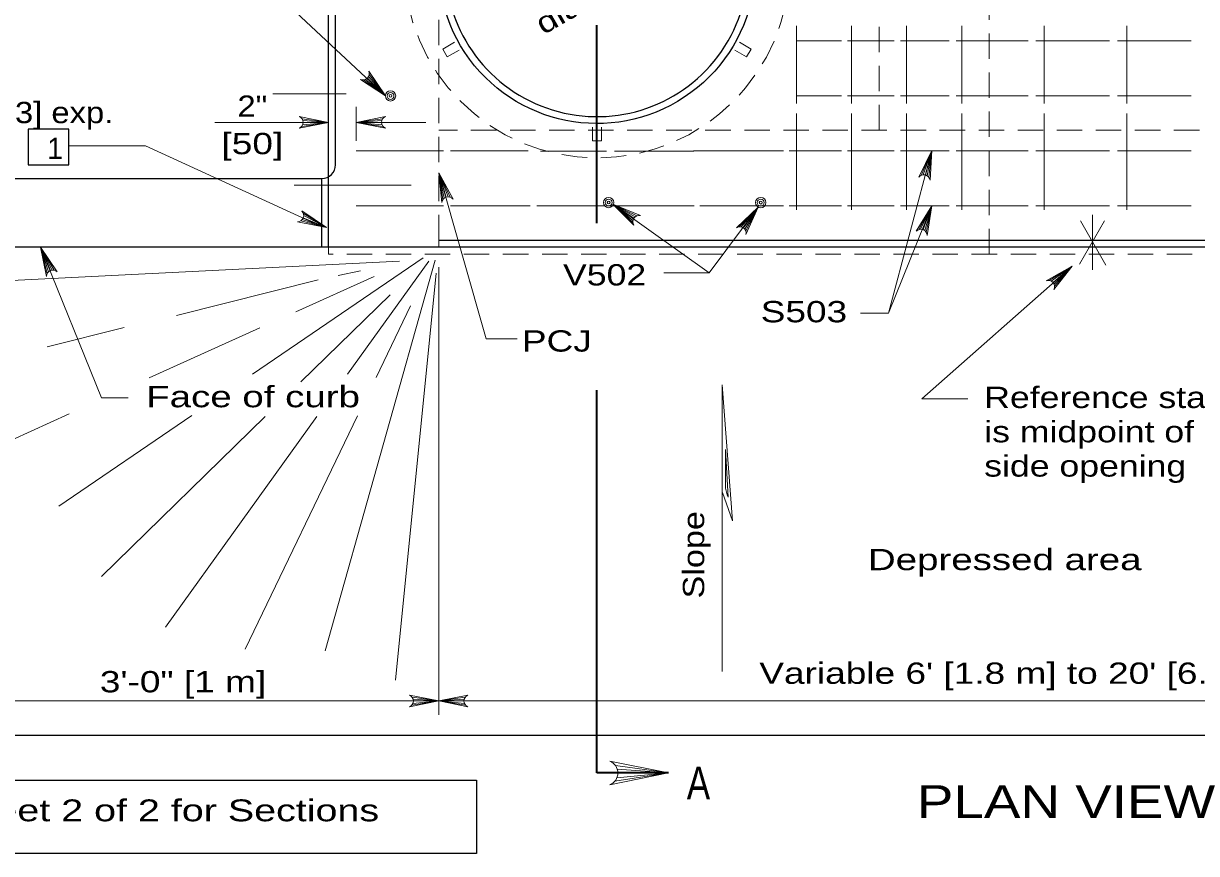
# Model space of a CAD drawing. Extents: x 758.3 to 792.3, y 849.7 to 893.7.
# Drawn here: x 762.67 to 771.26, y 882.61 to 888.69 of the extents above; entities that cross this region are included whole.
import ezdxf
from ezdxf.enums import TextEntityAlignment as Align

# ---------------------------------------------------------------- set-up
doc = ezdxf.new("R2010")
doc.units = 0
doc.header["$LTSCALE"] = 0.062
doc.linetypes.add('DOTTED', pattern=[1.5, 0.3, -1.2])
doc.linetypes.add('MEDIUM_DASHED', pattern=[4.5, 3, -1.5])
doc.layers.add('1', color=7, linetype='Continuous', lineweight=13)

msp = doc.modelspace()

# ---------------------------------------------------------------- linework, layer by layer
at = {"layer": '1', "lineweight": 25}
for p, q in [((764.9015, 887.05092), (764.9015, 891.08192)), ((764.95183, 887.65558), (764.95183, 891.0315)), ((761.99533, 887.55475), (764.85108, 887.55475)), ((764.85108, 887.05092), (764.85108, 887.55475)), ((775.28242, 887.10125), (765.70775, 887.10125)), ((767.821, 883.47342), (761.29283, 883.47342))]:
    msp.add_line(p, q, dxfattribs=at)
at = {"layer": '1', "linetype": 'MEDIUM_DASHED'}
for p, q in [((769.73917, 887.0005), (769.73917, 891.02758)), ((765.70775, 887.10125), (765.70775, 890.32608)), ((768.93292, 887.9075), (768.93292, 890.32608)), ((775.28242, 887.9075), (765.70775, 887.9075)), ((764.9015, 887.0005), (764.9015, 887.05092)), ((776.08867, 887.0005), (764.9015, 887.0005))]:
    msp.add_line(p, q, dxfattribs=at)
at = {"layer": '1'}
for p, q in [((765.31725, 888.15942), (764.66508, 888.76933)), ((768.32817, 888.10433), (768.32817, 888.67275)), ((768.73133, 888.10433), (768.73133, 888.67275)), ((769.1345, 888.10433), (769.1345, 888.67275)), ((769.53758, 888.10433), (769.53758, 888.67275)), ((770.14233, 888.10433), (770.14233, 888.67275)), ((770.74708, 888.10433), (770.74708, 888.67275)), ((768.65858, 888.5625), (768.32817, 888.5625)), ((769.04258, 888.5625), (768.70133, 888.5625)), ((769.4455, 888.5625), (769.09, 888.5625)), ((770.02392, 888.5625), (769.49775, 888.5625)), ((770.62125, 888.5625), (770.08075, 888.5625)), ((771.2185, 888.5625), (770.67808, 888.5625)), ((765.157, 888.27658), (765.31725, 888.15942)), ((765.17117, 888.28025), (765.31725, 888.15942)), ((765.18592, 888.29017), (765.31725, 888.15942)), ((765.19417, 888.30133), (765.31725, 888.15942)), ((765.19892, 888.3155), (765.31725, 888.15942)), ((764.49267, 888.17475), (765.03125, 888.17475)), ((768.65858, 888.15942), (768.32817, 888.15942)), ((769.04258, 888.15942), (768.70133, 888.15942)), ((769.4455, 888.15942), (769.09, 888.15942)), ((770.02392, 888.15942), (769.49775, 888.15942)), ((770.62125, 888.15942), (770.08075, 888.15942)), ((771.2185, 888.15942), (770.67808, 888.15942)), ((765.10308, 887.82992), (765.10308, 888.07867)), ((764.70758, 887.99258), (764.9015, 887.96542)), ((765.29692, 887.99258), (765.10308, 887.96542)), ((768.32817, 887.32383), (768.32817, 888.03133)), ((768.73133, 887.32383), (768.73133, 888.03133)), ((769.1345, 887.32383), (769.1345, 888.03133)), ((769.53758, 887.32383), (769.53758, 888.03133)), ((770.14233, 887.32383), (770.14233, 888.03133)), ((770.74708, 887.32383), (770.74708, 888.03133)), ((764.9015, 887.96542), (764.06942, 887.96542)), ((764.70533, 887.93542), (764.9015, 887.96542)), ((764.71275, 887.948), (764.9015, 887.96542)), ((764.71417, 887.97917), (764.9015, 887.96542)), ((764.71617, 887.96542), (764.9015, 887.96542)), ((765.29033, 887.97917), (765.10308, 887.96542)), ((765.614, 887.96542), (765.10308, 887.96542)), ((765.28833, 887.96542), (765.10308, 887.96542)), ((765.29183, 887.948), (765.10308, 887.96542)), ((765.29925, 887.93542), (765.10308, 887.96542)), ((765.74292, 887.75633), (765.10308, 887.75633)), ((766.364, 887.75633), (765.795, 887.75633)), ((766.93733, 887.75558), (766.45375, 887.75558)), ((767.57733, 887.75558), (766.99425, 887.75558)), ((768.23183, 887.75633), (767.57283, 887.75633)), ((768.65858, 887.75633), (768.2745, 887.75633)), ((769.04258, 887.75633), (768.70133, 887.75633)), ((769.31983, 887.75925), (769.00292, 886.569)), ((769.4455, 887.75633), (769.09, 887.75633)), ((769.24083, 887.57717), (769.31983, 887.75925)), ((769.25492, 887.58117), (769.31983, 887.75925)), ((769.27258, 887.58), (769.31983, 887.75925)), ((769.28533, 887.57458), (769.31983, 887.75925)), ((769.29667, 887.56483), (769.31983, 887.75925)), ((770.02392, 887.75633), (769.49775, 887.75633)), ((770.62125, 887.75633), (770.08075, 887.75633)), ((771.2185, 887.75633), (770.67808, 887.75633)), ((765.76358, 887.41825), (765.71, 887.59567)), ((765.74792, 887.41), (765.71, 887.59567)), ((765.738, 887.39925), (765.71, 887.59567)), ((765.77725, 887.42033), (765.71, 887.59567)), ((765.792, 887.41792), (765.71, 887.59567)), ((764.6495, 887.50442), (765.50617, 887.50442)), ((764.71708, 887.29767), (764.88717, 887.19533)), ((765.74292, 887.35325), (765.10308, 887.35325)), ((766.37817, 887.35325), (765.795, 887.35325)), ((766.91858, 887.35325), (766.42558, 887.35325)), ((767.5775, 887.35325), (766.95208, 887.35325)), ((766.98317, 887.36617), (767.68892, 886.86308)), ((767.1375, 887.26342), (766.98317, 887.36617)), ((767.13067, 887.247), (766.98317, 887.36617)), ((767.12992, 887.23242), (766.98317, 887.36617)), ((767.14675, 887.27375), (766.98317, 887.36617)), ((767.15967, 887.28125), (766.98317, 887.36617)), ((768.23183, 887.35325), (767.62025, 887.35325)), ((768.04667, 887.34367), (767.68892, 886.86308)), ((767.90858, 887.20117), (768.04667, 887.34367)), ((767.92308, 887.19992), (768.04667, 887.34367)), ((767.93933, 887.19258), (768.04667, 887.34367)), ((767.94933, 887.18308), (768.04667, 887.34367)), ((767.95642, 887.16992), (768.04667, 887.34367)), ((768.65858, 887.35325), (768.2745, 887.35325)), ((769.04258, 887.35325), (768.70133, 887.35325)), ((769.4455, 887.35325), (769.09, 887.35325)), ((769.22292, 887.18), (769.31983, 887.35325)), ((769.23725, 887.18258), (769.31983, 887.35325)), ((769.25483, 887.17967), (769.31983, 887.35325)), ((769.26692, 887.173), (769.31983, 887.35325)), ((769.27717, 887.16217), (769.31983, 887.35325)), ((770.02392, 887.35325), (769.49775, 887.35325)), ((770.62125, 887.35325), (770.08075, 887.35325)), ((771.2185, 887.35325), (770.67808, 887.35325)), ((764.6975, 887.24392), (764.88717, 887.19533)), ((764.70867, 887.25383), (764.88717, 887.19533)), ((764.71575, 887.26575), (764.88717, 887.19533)), ((764.71925, 887.28317), (764.88717, 887.19533)), ((770.39967, 886.92633), (770.58275, 887.2435)), ((770.59433, 886.91958), (770.40742, 887.24358)), ((770.49508, 886.886), (770.49508, 887.28817)), ((762.86417, 886.8805), (762.79133, 887.05092)), ((762.8495, 886.8705), (762.79133, 887.05092)), ((762.84092, 886.85875), (762.79133, 887.05092)), ((762.87758, 886.88408), (762.79133, 887.05092)), ((762.8925, 886.88333), (762.79133, 887.05092)), ((765.70775, 887.10125), (765.70775, 887.05092)), ((765.59425, 886.97317), (764.34517, 886.12125)), ((764.87708, 884.095), (765.68167, 886.95608)), ((765.42125, 886.94958), (762.2115, 886.78842)), ((765.13517, 886.87908), (764.97175, 886.84358)), ((765.04, 886.12125), (765.635, 886.949)), ((765.70775, 886.906), (765.70775, 883.62567)), ((770.17925, 886.80733), (770.34758, 886.91242)), ((770.19308, 886.80267), (770.34758, 886.91242)), ((770.207, 886.79167), (770.34758, 886.91242)), ((770.21442, 886.78), (770.34758, 886.91242)), ((770.21817, 886.7655), (770.34758, 886.91242)), ((764.82542, 886.81183), (763.78675, 886.5515)), ((765.23533, 886.83758), (764.662, 886.57875)), ((765.39142, 883.879), (765.68925, 886.86025)), ((767.35592, 886.86308), (767.68892, 886.86308)), ((765.35142, 886.70275), (764.69825, 886.06542)), ((765.24917, 886.09717), (765.50158, 886.6215)), ((763.40433, 886.46392), (762.84192, 886.32058)), ((764.39883, 886.45992), (763.587, 886.0935)), ((763.002, 885.82942), (762.58433, 885.64092)), ((763.89933, 885.81725), (762.9265, 885.15367)), ((764.43733, 885.81083), (763.23742, 884.63983)), ((763.70733, 884.26717), (764.81608, 885.80975)), ((764.29125, 884.107), (765.11425, 885.81692)), ((764.05883, 883.72683), (762.0795, 883.72683)), ((765.51158, 883.69683), (765.70775, 883.72683)), ((765.51383, 883.75392), (765.70775, 883.72683)), ((765.519, 883.70942), (765.70775, 883.72683)), ((765.52042, 883.7405), (765.70775, 883.72683)), ((765.52242, 883.72683), (765.70775, 883.72683)), ((765.90167, 883.75392), (765.70775, 883.72683)), ((765.89508, 883.7405), (765.70775, 883.72683)), ((765.89308, 883.72683), (765.70775, 883.72683)), ((765.8965, 883.70942), (765.70775, 883.72683)), ((765.90392, 883.69683), (765.70775, 883.72683)), ((766.998, 883.13942), (767.39033, 883.19933)), ((767.0025, 883.25367), (767.39033, 883.19933)), ((767.01283, 883.1645), (767.39033, 883.19933)), ((767.01567, 883.22675), (767.39033, 883.19933)), ((767.01967, 883.19933), (767.39033, 883.19933))]:
    msp.add_line(p, q, dxfattribs=at)
at = {"layer": '1', "lineweight": 35}
for p, q in [((766.86683, 887.22775), (766.86683, 888.67825)), ((766.86683, 884.62375), (766.86683, 886.00475)), ((766.86683, 883.19933), (766.86683, 884.62375)), ((767.39033, 883.19933), (766.86683, 883.19933))]:
    msp.add_line(p, q, dxfattribs=at)
at = {"layer": '1', "linetype": 'DOTTED'}
for p, q in [((765.73742, 888.5025), (765.8465, 888.56533)), ((765.73742, 888.5025), (765.77067, 888.44483)), ((765.77067, 888.44483), (765.87983, 888.50767)), ((767.96283, 888.44525), (767.85367, 888.50833)), ((767.99608, 888.50292), (767.88692, 888.566)), ((767.96283, 888.44525), (767.99608, 888.50292)), ((766.8335, 887.83133), (766.8335, 887.95725)), ((766.90008, 887.83133), (766.90008, 887.95725)), ((766.8335, 887.83133), (766.90008, 887.83133))]:
    msp.add_line(p, q, dxfattribs=at)
at = {"layer": '1'}
for points in [[(765.13525, 888.28017), (765.31725, 888.15942), (765.19567, 888.34092)], [(764.68733, 887.92258), (764.9015, 887.96542), (764.68733, 888.00825)], [(765.31725, 887.92258), (765.10308, 887.96542), (765.31725, 888.00825)], [(764.85508, 887.19967), (763.56142, 887.79375), (763.00008, 887.79375)], [(769.22383, 887.56308), (769.31983, 887.75925), (769.30667, 887.54125)], [(765.73092, 887.37825), (765.71, 887.59567), (765.81292, 887.40308)], [(765.71, 887.59567), (766.05583, 886.37908), (766.28267, 886.37908)], [(764.70533, 887.31633), (764.88717, 887.19533), (764.67275, 887.23717)], [(767.13775, 887.21175), (766.98317, 887.36617), (767.18525, 887.28308)], [(767.88767, 887.19392), (768.04667, 887.34367), (767.9575, 887.14425)], [(769.31983, 887.35325), (769.00292, 886.569), (768.79558, 886.569)], [(769.20458, 887.16767), (769.31983, 887.35325), (769.28475, 887.13767)], [(762.79133, 887.05092), (763.23917, 885.94675), (763.43358, 885.94675)], [(762.83617, 886.83717), (762.79133, 887.05092), (762.91492, 886.87083)], [(770.34758, 886.91242), (769.246, 885.93983), (769.58292, 885.93983)], [(770.15725, 886.80533), (770.34758, 886.91242), (770.21308, 886.74033)], [(767.784, 883.94183), (767.784, 886.0425), (767.85975, 885.04617), (767.78708, 885.25342)], [(767.82808, 885.22033), (767.80917, 885.56842), (767.80917, 885.28625), (767.82175, 885.22633)], [(771.9685, 883.72683), (765.70775, 883.72683), (764.05883, 883.72683)], [(765.49358, 883.684), (765.70775, 883.72683), (765.49358, 883.76967)], [(765.92192, 883.684), (765.70775, 883.72683), (765.92192, 883.76967)], [(766.962, 883.11367), (767.39033, 883.19933), (766.962, 883.285)]]:
    msp.add_lwpolyline(points, dxfattribs=at)
at = {"layer": '1', "lineweight": 25}
for points in [[(762.7015, 887.91608), (762.7015, 887.6545), (763.00008, 887.6545), (763.00008, 887.91608)], [(761.3445, 883.14692), (765.98558, 883.14692), (765.98558, 882.60908), (761.3445, 882.60908)]]:
    msp.add_lwpolyline(points, close=True, dxfattribs=at)
for points in [[(779.047, 887.05092), (775.87267, 887.05092), (761.99533, 887.05092)], [(779.072, 883.47342), (773.49217, 883.47342), (767.821, 883.47342)]]:
    msp.add_lwpolyline(points, dxfattribs=at)
at = {"layer": '1'}
for centre, radius, start, end in [((765.15321, 888.32277), 0.04623, 247.21295, 23.03908), ((764.67001, 887.96548), 0.04623, 292.08605, 67.91218), ((765.33451, 887.96548), 0.04623, 112.08782, 247.91395), ((769.26091, 887.53541), 0.04623, 7.32988, 143.15601), ((765.77698, 887.37414), 0.04623, 38.90216, 174.72829), ((764.67306, 887.28328), 0.04623, 269.73792, 45.56404), ((767.17591, 887.2379), 0.04623, 78.43623, 214.26236), ((767.9126, 887.15499), 0.04623, 346.67151, 122.49763), ((769.23865, 887.13646), 0.04623, 1.54741, 137.37354), ((762.88239, 886.8381), 0.04623, 45.24491, 181.07103), ((770.17205, 886.76157), 0.04623, 332.74494, 108.57107), ((765.47629, 883.72688), 0.04623, 292.08605, 67.91218), ((765.93922, 883.72688), 0.04623, 112.08782, 247.91395), ((766.92739, 883.19947), 0.09245, 292.08605, 67.91218)]:
    msp.add_arc(centre, radius, start, end, dxfattribs=at)
at = {"layer": '1', "linetype": 'MEDIUM_DASHED'}
msp.add_ellipse((766.8668, 889.11609), major_axis=(1.411, 0), ratio=0.999895, dxfattribs=at)
at = {"layer": '1', "lineweight": 25}
for centre, major_axis, start_param, end_param in [((766.8668, 889.11609), (1.15904, 0), 0.6356568, 6.9188421), ((766.8668, 889.11609), (1.10864, 0), 3.1884629, 6.9841396), ((764.85108, 887.65555), (0.10079, 0), 4.712389, 6.2831853)]:
    msp.add_ellipse(centre, major_axis=major_axis, ratio=0.999895, start_param=start_param, end_param=end_param, dxfattribs=at)
at = {"layer": '1'}
for centre, major_axis in [((765.35501, 888.15943), (0.03779, 0)), ((765.35501, 888.15943), (0.0252, 0)), ((765.35501, 888.15943), (0.01008, 0)), ((766.95246, 887.37842), (0.03779, 0)), ((766.95246, 887.37842), (0.0252, 0)), ((766.95246, 887.37842), (0.01008, 0)), ((768.06595, 887.37761), (0.03779, 0)), ((768.06595, 887.37761), (-0.0252, 0)), ((768.06595, 887.37761), (0.01008, 0))]:
    msp.add_ellipse(centre, major_axis=major_axis, ratio=0.999895, dxfattribs=at)

# ---------------------------------------------------------------- texts
at = {"layer": '1', "width": 1.25}
msp.add_text('dia. cover', height=0.156, rotation=29.997, dxfattribs=at).set_placement((766.96438, 888.88672), align=Align.CENTER)
at = {"layer": '1'}
for s, width, p in [('2"', 1.15, (764.34333, 888.00633)), ('[50]', 1.3, (764.34342, 887.73233))]:
    msp.add_text(s, height=0.156, dxfattribs=dict(at, width=width)).set_placement(p, align=Align.CENTER)
for s, height, width, p in [('1/2" [13] exp.', 0.156, 1.15, (761.9195, 887.95983)), ('V502', 0.156, 1.25, (766.61833, 886.77075)), ('S503', 0.156, 1.3, (768.06567, 886.50092)), (' PCJ', 0.156, 1.3, (766.2415, 886.28625)), ('Face of curb', 0.156, 1.35, (763.566, 885.87858)), ('Reference station', 0.156, 1.25, (769.70283, 885.87283)), ('is midpoint of', 0.156, 1.25, (769.70283, 885.62167)), ('side opening', 0.156, 1.25, (769.70283, 885.3705)), ('Depressed area', 0.156, 1.35, (768.85108, 884.68508)), ('3\'-0" [1 m]', 0.156, 1.3, (763.22658, 883.79008)), ("Variable 6' [1.8 m] to 20' [6.0 m]", 0.156, 1.3, (768.0555, 883.85242)), ('A', 0.24, 0.8, (767.52458, 883.0055)), ('PLAN VIEW', 0.24, 1.25, (769.20967, 882.86992)), ('See Sheet 2 of 2 for Sections', 0.16, 1.35, (761.51425, 882.84542))]:
    msp.add_text(s, height=height, dxfattribs=dict(at, width=width)).set_placement(p)
msp.add_text('1', height=0.156, dxfattribs=at).set_placement((762.84025, 887.697))
at = {"layer": '1', "width": 1.2}
msp.add_text('Slope', height=0.156, rotation=90, dxfattribs=at).set_placement((767.65208, 884.47775))

doc.saveas('drawing.dxf')
